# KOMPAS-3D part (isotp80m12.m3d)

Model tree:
1. XY Plane
2. ZX Plane
3. ZY Plane
4. X Axis
5. Y Axis
6. Z Axis
7. Origin
8. Operation without History:1  (labels: nVent ERIFLEX / ISOTP80M12; ISOTP80M12)

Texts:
  nVent ERIFLEX / ISOTP80M12
  ISO-TP Low Voltage Insulators, Metric Thread, 3.15", 65 mm Hex Width, M12 Thread
  Steel; Glass Fibre Reinforced Polyamide
  ISOTP80M12
  https://www.nvent.com/eriflex/products/efsISOTP80M12
  CE, Eriflex ISOTP; CSA-Comp; IEC 61439-1; RoHS; UR; cUR
  ISO-TP Low Voltage Insulators, Metric Thread
  90-24062020-026068CUJF4C89KACNKNCUBE8JVUTQ
  Plane through Three Vertices
  Plane at Angle
  Plane through Edge and Vertex
  Axis through Two Vertices
  Conical Surface Axis
  Axis through Edge
  Operation without History
  Array by Grid
  Axis on Intersection of Two Planes
  Plane through Two Edges
  Plane through Edge and Face
  Array by Concentric Grid
  Array along Curve
  Surface without history
  Surface of extrusion
  Surface of revolution
  Surface of cross-sections
  Bend in Line
  Hole in Sheet Body
  Cut in Sheet Body
  Point in CG
  Linear from Segment to Point
  Geometric Tolerance Symbol
  Bend by Sketch
  Junction of Curves
  Array by points
  Surface by point grid
  Point Group by Curve
  Surface by curve grid
  Point Group from File
  Curve Equidistant Line
  Surface by point stratum
  Axis through Vertex along Object
  Curve without History
  Plane Tangent at Point
  Plane through Plane Curve
  Point Group by Surface
  Distance and angle
  Array by table
  Curve by 2 projections
  Curve by law
  Isoparametric curve group
  Surface of connection
  Linear dimension of the operation
  Angular dimension of the operation
  Radial dimension of the operation
  Diameter dimension of the operation
  Linear dimension of the sketch
  Angular dimension of the sketch
  Angular dimension of the broken sketch
  Radial dimension of the sketch
  Radial dimension of the bent sketch
  Diameter dimension of the sketch
  Array by Sample
  Operation from library
  Linear dimension without history
  Angular dimension without history
  Radial dimension without history
  Diameter dimension without history
  Unspecified Surface Finish
  Linear dimension of the broken line
  Text on drawing
  Leader #1
  Leader #2
  Leader #3
  Shape Deviations and Datum
  Node point number
  Mark of coordination axis
  Node point designation
  Mark/reference number with leader
  Mark/reference number on line
  Mark/reference number without leader
  Report Table Header
  Report Table Cell
  Report table name
  Component from Library
  Macroelement 2D
  Surface finish not set
  Processing method not specified
  Delete material layer
  Without Material Removal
